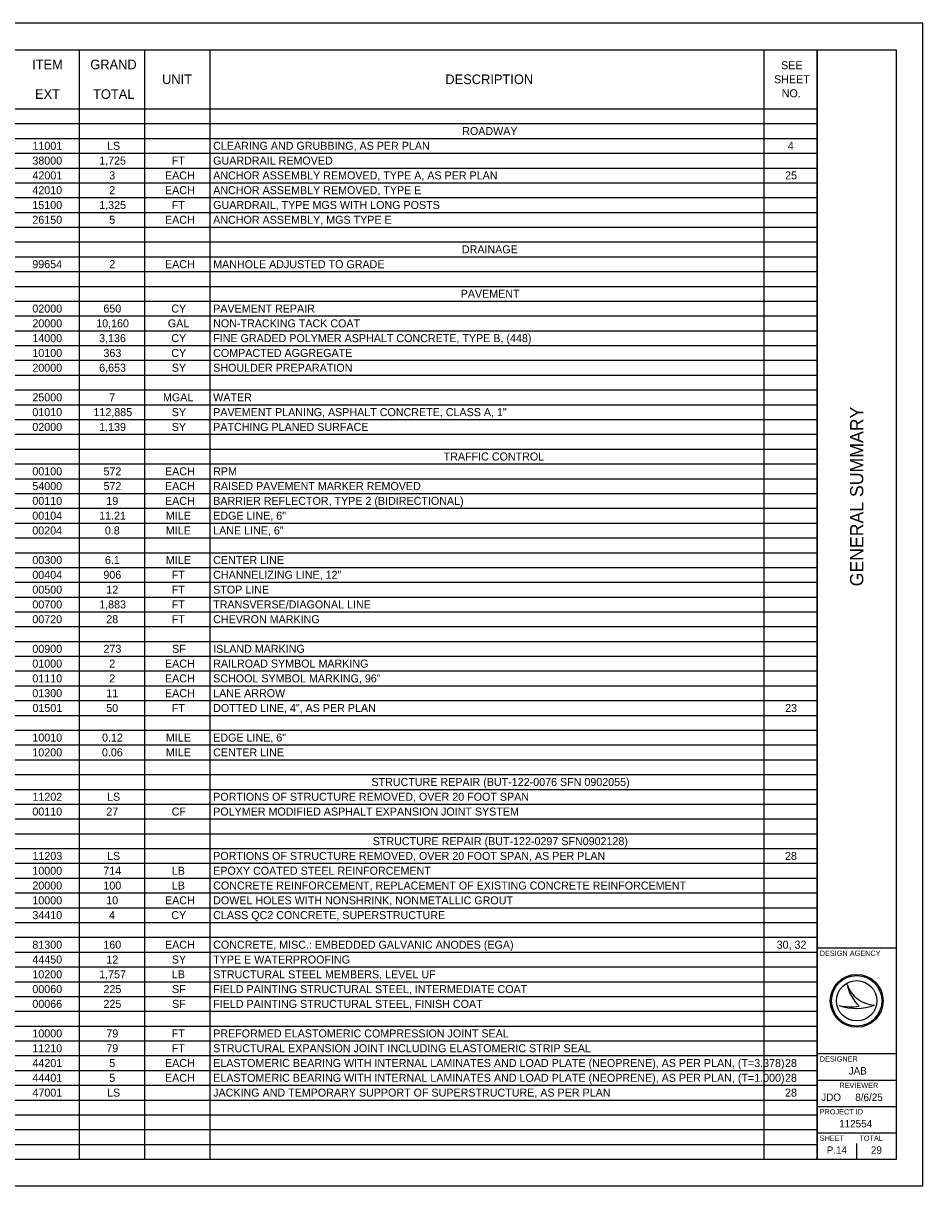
# Model space of a CAD drawing. Extents: x 45.7 to 120.9, y -0.1 to 21.9.
# Drawn here: x 62.68 to 79.7, y -0.09 to 21.91 of the extents above; entities that cross this region are included whole.
import ezdxf

# ---------------------------------------------------------------- set-up
doc = ezdxf.new("R2010")
doc.units = 0
for name, color, linetype in [('SH_Border', 7, 'Continuous'), ('SH_Cut_Line', 7, 'Continuous'), ('SH_Data', 7, 'Continuous'), ('SH_Text', 7, 'Continuous')]:
    doc.layers.add(name, color=color, linetype=linetype)

msp = doc.modelspace()

# ---------------------------------------------------------------- linework, layer by layer
at = {"layer": 'SH_Border'}
for p, q in [((77.703, 0.409), (77.703, 21.409)), ((77.703, 4.409), (79.203, 4.409)), ((77.703, 2.409), (79.203, 2.409)), ((77.703, 1.909), (79.203, 1.909)), ((77.703, 1.409), (79.203, 1.409)), ((77.703, 0.909), (79.203, 0.909))]:
    msp.add_line(p, q, dxfattribs=at)
msp.add_lwpolyline([(47.203, 21.409), (79.203, 21.409), (79.203, 0.409), (47.203, 0.409)], close=True, dxfattribs=at)
at = {"layer": 'SH_Cut_Line'}
msp.add_lwpolyline([(45.703, -0.091), (79.703, -0.091), (79.703, 21.909), (45.703, 21.909)], close=True, dxfattribs=at)
at = {"layer": 'SH_Data'}
for p, q in [((78.27, 3.719), (78.27, 3.719)), ((78.12, 3.319), (78.12, 3.319)), ((78.453, 3.409), (78.453, 3.409)), ((78.79, 3.328), (78.79, 3.328)), ((78.453, 0.409), (78.453, 0.709)), ((78.078, 0.584), (78.078, 0.584))]:
    msp.add_line(p, q, dxfattribs=at)
for radius in [0.5, 0.477, 0.477, 0.382]:
    msp.add_circle((78.453, 3.409), radius, dxfattribs=at)
for centre, radius, start, end in [((78.819, 3.907), 0.58, 198.9257, 198.9319), ((79.05, 3.879), 0.796, 191.6379, 191.6421), ((78.819, 3.907), 0.58, 198.9319, 267.1657), ((79.05, 3.879), 0.796, 191.6421, 226.0947), ((78.442, 4.279), 1.013, 251.4576, 290.0832), ((78.351, 4.563), 1.266, 259.4964, 259.4995), ((78.442, 4.279), 1.013, 251.4527, 251.4576), ((78.351, 4.563), 1.266, 259.4995, 276.6672)]:
    msp.add_arc(centre, radius, start, end, dxfattribs=at)
at = {"layer": 'SH_Text'}
for p, q in [((47.203, 21.409), (77.703, 21.409)), ((63.738, 21.409), (63.738, 0.412)), ((64.973, 21.409), (64.973, 0.412)), ((66.208, 21.409), (66.208, 0.412)), ((76.698, 21.409), (76.698, 0.412)), ((77.703, 21.409), (77.703, 0.412)), ((47.203, 20.289), (77.703, 20.289)), ((47.203, 20.009), (77.703, 20.009)), ((47.203, 19.729), (77.703, 19.729)), ((47.203, 19.449), (77.703, 19.449)), ((47.203, 19.169), (77.703, 19.169)), ((47.203, 18.889), (77.703, 18.889)), ((47.203, 18.609), (77.703, 18.609)), ((47.203, 18.33), (77.703, 18.33)), ((47.203, 18.05), (77.703, 18.05)), ((47.203, 17.77), (77.703, 17.77)), ((47.203, 17.49), (77.703, 17.49)), ((47.203, 17.21), (77.703, 17.21)), ((47.203, 16.93), (77.703, 16.93)), ((47.203, 16.65), (77.703, 16.65)), ((47.203, 16.37), (77.703, 16.37)), ((47.203, 16.09), (77.703, 16.09)), ((47.203, 15.81), (77.703, 15.81)), ((47.203, 15.53), (77.703, 15.53)), ((47.203, 15.25), (77.703, 15.25)), ((47.203, 14.97), (77.703, 14.97)), ((47.203, 14.69), (77.703, 14.69)), ((47.203, 14.41), (77.703, 14.41)), ((47.203, 14.13), (77.703, 14.13)), ((47.203, 13.85), (77.703, 13.85)), ((47.203, 13.57), (77.703, 13.57)), ((47.203, 13.29), (77.703, 13.29)), ((47.203, 13.01), (77.703, 13.01)), ((47.203, 12.73), (77.703, 12.73)), ((47.203, 12.45), (77.703, 12.45)), ((47.203, 12.17), (77.703, 12.17)), ((47.203, 11.89), (77.703, 11.89)), ((47.203, 11.61), (77.703, 11.61)), ((47.203, 11.33), (77.703, 11.33)), ((47.203, 11.05), (77.703, 11.05)), ((47.203, 10.77), (77.703, 10.77)), ((47.203, 10.49), (77.703, 10.49)), ((47.203, 10.21), (77.703, 10.21)), ((47.203, 9.93), (77.703, 9.93)), ((47.203, 9.651), (77.703, 9.651)), ((47.203, 9.371), (77.703, 9.371)), ((47.203, 9.091), (77.703, 9.091)), ((47.203, 8.811), (77.703, 8.811)), ((47.203, 8.531), (77.703, 8.531)), ((47.203, 8.251), (77.703, 8.251)), ((47.203, 7.971), (77.703, 7.971)), ((47.203, 7.691), (77.703, 7.691)), ((47.203, 7.411), (77.703, 7.411)), ((47.203, 7.131), (77.703, 7.131)), ((47.203, 6.851), (77.703, 6.851)), ((47.203, 6.571), (77.703, 6.571)), ((47.203, 6.291), (77.703, 6.291)), ((47.203, 6.011), (77.703, 6.011)), ((47.203, 5.731), (77.703, 5.731)), ((47.203, 5.451), (77.703, 5.451)), ((47.203, 5.171), (77.703, 5.171)), ((47.203, 4.891), (77.703, 4.891)), ((47.203, 4.611), (77.703, 4.611)), ((47.203, 4.331), (77.703, 4.331)), ((47.203, 4.051), (77.703, 4.051)), ((47.203, 3.771), (77.703, 3.771)), ((47.203, 3.491), (77.703, 3.491)), ((47.203, 3.211), (77.703, 3.211)), ((47.203, 2.931), (77.703, 2.931)), ((47.203, 2.651), (77.703, 2.651)), ((47.203, 2.371), (77.703, 2.371)), ((47.203, 2.091), (77.703, 2.091)), ((47.203, 1.811), (77.703, 1.811)), ((47.203, 1.531), (77.703, 1.531)), ((47.203, 1.251), (77.703, 1.251)), ((47.203, 0.972), (77.703, 0.972)), ((47.203, 0.692), (77.703, 0.692)), ((47.203, 0.412), (77.703, 0.412))]:
    msp.add_line(p, q, dxfattribs=at)

# ---------------------------------------------------------------- texts
at = {"layer": 'SH_Data'}
msp.add_text('GENERAL SUMMARY', height=0.25, rotation=90, dxfattribs=at).set_placement((78.578, 11.253))
for s, height, p in [('DESIGN AGENCY', 0.1, (77.753, 4.259)), ('DESIGNER', 0.1, (77.753, 2.259)), ('JAB', 0.14, (78.301, 2.014)), ('REVIEWER', 0.1, (78.125, 1.759)), ('JDO', 0.14, (77.782, 1.514)), ('8/6/25', 0.14, (78.426, 1.514)), ('PROJECT ID', 0.1, (77.753, 1.259)), ('112554', 0.14, (78.121, 1.014)), ('SHEET', 0.1, (77.753, 0.759)), ('TOTAL', 0.1, (78.503, 0.759)), ('P.14', 0.14, (77.885, 0.514)), ('29', 0.14, (78.722, 0.514))]:
    msp.add_text(s, height=height, dxfattribs=at).set_placement(p)
at = {"layer": 'SH_Text'}
for s, height, p in [('ITEM', 0.1818, (62.848, 21.038)), ('GRAND', 0.1818, (63.948, 21.038)), ('SEE ', 0.1515, (77.023, 21.039)), ('UNIT', 0.1818, (65.307, 20.758)), ('DESCRIPTION', 0.18181, (70.668, 20.758)), ('SHEET ', 0.1515, (76.89, 20.773)), ('EXT', 0.1818, (62.902, 20.478)), ('TOTAL', 0.1818, (64, 20.478)), ('NO.', 0.1515, (77.034, 20.508)), ('ROADWAY', 0.1515, (70.987, 19.794)), ('11001', 0.1515, (62.854, 19.514)), ('LS', 0.1515, (64.265, 19.514)), ('CLEARING AND GRUBBING, AS PER PLAN', 0.15151, (66.274, 19.514)), ('4', 0.152, (77.149, 19.514)), ('38000', 0.1515, (62.852, 19.234)), ('1,725', 0.1515, (64.117, 19.234)), ('FT', 0.1515, (65.489, 19.234)), ('GUARDRAIL REMOVED', 0.15151, (66.274, 19.234)), ('42001', 0.1515, (62.854, 18.954)), ('3', 0.152, (64.307, 18.954)), ('EACH', 0.1515, (65.362, 18.954)), ('ANCHOR ASSEMBLY REMOVED, TYPE A, AS PER PLAN', 0.15151, (66.274, 18.954)), ('25', 0.1515, (77.098, 18.954)), ('42010', 0.1515, (62.852, 18.674)), ('2', 0.152, (64.307, 18.674)), ('EACH', 0.1515, (65.362, 18.674)), ('ANCHOR ASSEMBLY REMOVED, TYPE E', 0.15151, (66.274, 18.674)), ('15100', 0.1515, (62.852, 18.394)), ('1,325', 0.1515, (64.117, 18.394)), ('FT', 0.1515, (65.489, 18.394)), ('GUARDRAIL, TYPE MGS WITH LONG POSTS', 0.15151, (66.274, 18.394)), ('26150', 0.1515, (62.852, 18.114)), ('5', 0.152, (64.307, 18.114)), ('EACH', 0.1515, (65.362, 18.114)), ('ANCHOR ASSEMBLY, MGS TYPE E', 0.15151, (66.274, 18.114)), ('DRAINAGE', 0.1515, (70.981, 17.554)), ('99654', 0.1515, (62.851, 17.274)), ('2', 0.152, (64.307, 17.274)), ('EACH', 0.1515, (65.362, 17.274)), ('MANHOLE ADJUSTED TO GRADE', 0.15151, (66.274, 17.274)), ('PAVEMENT', 0.1515, (70.958, 16.714)), ('02000', 0.1515, (62.852, 16.434)), ('650', 0.1515, (64.196, 16.434)), ('CY', 0.1515, (65.482, 16.434)), ('PAVEMENT REPAIR', 0.15151, (66.274, 16.434)), ('20000', 0.1515, (62.852, 16.154)), ('10,160', 0.1515, (64.06, 16.154)), ('GAL', 0.1515, (65.416, 16.154)), ('NON-TRACKING TACK COAT', 0.15151, (66.274, 16.154)), ('14000', 0.1515, (62.852, 15.874)), ('3,136', 0.1515, (64.115, 15.874)), ('CY', 0.1515, (65.482, 15.874)), ('FINE GRADED POLYMER ASPHALT CONCRETE, TYPE B, (448)', 0.15151, (66.274, 15.874)), ('10100', 0.1515, (62.852, 15.594)), ('363', 0.1515, (64.198, 15.594)), ('CY', 0.1515, (65.482, 15.594)), ('COMPACTED AGGREGATE', 0.15151, (66.274, 15.594)), ('20000', 0.1515, (62.852, 15.314)), ('6,653', 0.1515, (64.117, 15.314)), ('SY', 0.1515, (65.491, 15.314)), ('SHOULDER PREPARATION', 0.15151, (66.274, 15.314)), ('25000', 0.1515, (62.852, 14.754)), ('7', 0.152, (64.306, 14.754)), ('MGAL', 0.1515, (65.324, 14.754)), ('WATER', 0.1515, (66.274, 14.754)), ('01010', 0.1515, (62.852, 14.474)), ('112,885', 0.1515, (64.008, 14.474)), ('SY', 0.1515, (65.491, 14.474)), ('PAVEMENT PLANING, ASPHALT CONCRETE, CLASS A, 1"', 0.15151, (66.274, 14.474)), ('02000', 0.1515, (62.852, 14.194)), ('1,139', 0.1515, (64.116, 14.194)), ('SY', 0.1515, (65.491, 14.194)), ('PATCHING PLANED SURFACE', 0.15151, (66.274, 14.194)), ('TRAFFIC CONTROL', 0.15151, (70.636, 13.634)), ('00100', 0.1515, (62.852, 13.354)), ('572', 0.1515, (64.198, 13.354)), ('EACH', 0.1515, (65.362, 13.354)), ('RPM', 0.1515, (66.274, 13.354)), ('54000', 0.1515, (62.852, 13.074)), ('572', 0.1515, (64.198, 13.074)), ('EACH', 0.1515, (65.362, 13.074)), ('RAISED PAVEMENT MARKER REMOVED', 0.15151, (66.274, 13.074)), ('00110', 0.1515, (62.852, 12.794)), ('19', 0.1515, (64.252, 12.794)), ('EACH', 0.1515, (65.362, 12.794)), ('BARRIER REFLECTOR, TYPE 2 (BIDIRECTIONAL)', 0.15151, (66.274, 12.794)), ('00104', 0.1515, (62.851, 12.514)), ('11.21', 0.1515, (64.116, 12.514)), ('MILE', 0.1515, (65.379, 12.514)), ('EDGE LINE, 6"', 0.15151, (66.274, 12.514)), ('00204', 0.1515, (62.851, 12.234)), ('0.8', 0.1515, (64.224, 12.234)), ('MILE', 0.1515, (65.379, 12.234)), ('LANE LINE, 6"', 0.15151, (66.274, 12.234)), ('00300', 0.1515, (62.852, 11.675)), ('6.1', 0.1515, (64.225, 11.675)), ('MILE', 0.1515, (65.379, 11.675)), ('CENTER LINE', 0.15151, (66.274, 11.675)), ('00404', 0.1515, (62.851, 11.395)), ('906', 0.1515, (64.196, 11.395)), ('FT', 0.1515, (65.489, 11.395)), ('CHANNELIZING LINE, 12"', 0.15151, (66.274, 11.395)), ('00500', 0.1515, (62.852, 11.115)), ('12', 0.1515, (64.252, 11.115)), ('FT', 0.1515, (65.489, 11.115)), ('STOP LINE', 0.1515, (66.274, 11.115)), ('00700', 0.1515, (62.852, 10.835)), ('1,883', 0.1515, (64.117, 10.835)), ('FT', 0.1515, (65.489, 10.835)), ('TRANSVERSE/DIAGONAL LINE', 0.15151, (66.274, 10.835)), ('00720', 0.1515, (62.852, 10.555)), ('28', 0.1515, (64.251, 10.555)), ('FT', 0.1515, (65.489, 10.555)), ('CHEVRON MARKING', 0.15151, (66.274, 10.555)), ('00900', 0.1515, (62.852, 9.995)), ('273', 0.1515, (64.198, 9.995)), ('SF', 0.1515, (65.496, 9.995)), ('ISLAND MARKING', 0.15151, (66.274, 9.995)), ('01000', 0.1515, (62.852, 9.715)), ('2', 0.152, (64.307, 9.715)), ('EACH', 0.1515, (65.362, 9.715)), ('RAILROAD SYMBOL MARKING', 0.15151, (66.274, 9.715)), ('01110', 0.1515, (62.852, 9.435)), ('2', 0.152, (64.307, 9.435)), ('EACH', 0.1515, (65.362, 9.435)), ('SCHOOL SYMBOL MARKING, 96"', 0.15151, (66.274, 9.435)), ('01300', 0.1515, (62.852, 9.155)), ('11', 0.1515, (64.252, 9.155)), ('EACH', 0.1515, (65.362, 9.155)), ('LANE ARROW', 0.1515, (66.274, 9.155)), ('01501', 0.1515, (62.854, 8.875)), ('50', 0.1515, (64.25, 8.875)), ('FT', 0.1515, (65.489, 8.875)), ('DOTTED LINE, 4", AS PER PLAN', 0.15151, (66.274, 8.875)), ('23', 0.1515, (77.098, 8.875)), ('10010', 0.1515, (62.852, 8.315)), ('0.12', 0.1515, (64.171, 8.315)), ('MILE', 0.1515, (65.379, 8.315)), ('EDGE LINE, 6"', 0.15151, (66.274, 8.315)), ('10200', 0.1515, (62.852, 8.035)), ('0.06', 0.1515, (64.169, 8.035)), ('MILE', 0.1515, (65.379, 8.035)), ('CENTER LINE', 0.15151, (66.274, 8.035)), ('STRUCTURE REPAIR (BUT-122-0076 SFN 0902055)', 0.15151, (69.269, 7.475)), ('11202', 0.1515, (62.854, 7.195)), ('LS', 0.1515, (64.265, 7.195)), ('PORTIONS OF STRUCTURE REMOVED, OVER 20 FOOT SPAN', 0.15151, (66.274, 7.195)), ('00110', 0.1515, (62.852, 6.915)), ('27', 0.1515, (64.251, 6.915)), ('CF', 0.1515, (65.488, 6.915)), ('POLYMER MODIFIED ASPHALT EXPANSION JOINT SYSTEM', 0.15151, (66.274, 6.915)), ('STRUCTURE REPAIR (BUT-122-0297 SFN0902128)', 0.15151, (69.293, 6.355)), ('11203', 0.1515, (62.854, 6.075)), ('LS', 0.1515, (64.265, 6.075)), ('PORTIONS OF STRUCTURE REMOVED, OVER 20 FOOT SPAN, AS PER PLAN', 0.15151, (66.274, 6.075)), ('28', 0.1515, (77.096, 6.075)), ('10000', 0.1515, (62.852, 5.795)), ('714', 0.1515, (64.195, 5.795)), ('LB', 0.1515, (65.491, 5.795)), ('EPOXY COATED STEEL REINFORCEMENT', 0.15151, (66.274, 5.795)), ('20000', 0.1515, (62.852, 5.515)), ('100', 0.1515, (64.196, 5.515)), ('LB', 0.1515, (65.491, 5.515)), ('CONCRETE REINFORCEMENT, REPLACEMENT OF EXISTING CONCRETE REINFORCEMENT', 0.15151, (66.274, 5.515)), ('10000', 0.1515, (62.852, 5.235)), ('10', 0.1515, (64.25, 5.235)), ('EACH', 0.1515, (65.362, 5.235)), ('DOWEL HOLES WITH NONSHRINK, NONMETALLIC GROUT', 0.15151, (66.274, 5.235)), ('34410', 0.1515, (62.852, 4.955)), ('4', 0.152, (64.304, 4.955)), ('CY', 0.1515, (65.482, 4.955)), ('CLASS QC2 CONCRETE, SUPERSTRUCTURE', 0.15151, (66.274, 4.955)), ('81300', 0.1515, (62.852, 4.395)), ('160', 0.1515, (64.196, 4.395)), ('EACH', 0.1515, (65.362, 4.395)), ('CONCRETE, MISC.: EMBEDDED GALVANIC ANODES (EGA)', 0.15151, (66.274, 4.395)), ('30, 32', 0.1515, (76.938, 4.395)), ('44450', 0.1515, (62.852, 4.115)), ('12', 0.1515, (64.252, 4.115)), ('SY', 0.1515, (65.491, 4.115)), ('TYPE E WATERPROOFING', 0.15151, (66.274, 4.115)), ('10200', 0.1515, (62.852, 3.835)), ('1,757', 0.1515, (64.116, 3.835)), ('LB', 0.1515, (65.491, 3.835)), ('STRUCTURAL STEEL MEMBERS, LEVEL UF', 0.15151, (66.274, 3.835)), ('00060', 0.1515, (62.852, 3.555)), ('225', 0.1515, (64.198, 3.555)), ('SF', 0.1515, (65.496, 3.555)), ('FIELD PAINTING STRUCTURAL STEEL, INTERMEDIATE COAT', 0.15151, (66.274, 3.555)), ('00066', 0.1515, (62.852, 3.275)), ('225', 0.1515, (64.198, 3.275)), ('SF', 0.1515, (65.496, 3.275)), ('FIELD PAINTING STRUCTURAL STEEL, FINISH COAT', 0.15151, (66.274, 3.275)), ('10000', 0.1515, (62.852, 2.716)), ('79', 0.1515, (64.252, 2.716)), ('FT', 0.1515, (65.489, 2.716)), ('PREFORMED ELASTOMERIC COMPRESSION JOINT SEAL', 0.15151, (66.274, 2.716)), ('11210', 0.1515, (62.852, 2.436)), ('79', 0.1515, (64.252, 2.436)), ('FT', 0.1515, (65.489, 2.436)), ('STRUCTURAL EXPANSION JOINT INCLUDING ELASTOMERIC STRIP SEAL', 0.15151, (66.274, 2.436)), ('44201', 0.1515, (62.854, 2.156)), ('5', 0.152, (64.307, 2.156)), ('EACH', 0.1515, (65.362, 2.156)), ('ELASTOMERIC BEARING WITH INTERNAL LAMINATES AND LOAD PLATE (NEOPRENE), AS PER PLAN, (T=3.378)', 0.15151, (66.274, 2.156)), ('28', 0.1515, (77.096, 2.156)), ('44401', 0.1515, (62.854, 1.876)), ('5', 0.152, (64.307, 1.876)), ('EACH', 0.1515, (65.362, 1.876)), ('ELASTOMERIC BEARING WITH INTERNAL LAMINATES AND LOAD PLATE (NEOPRENE), AS PER PLAN, (T=1.000)', 0.15151, (66.274, 1.876)), ('28', 0.1515, (77.096, 1.876)), ('47001', 0.1515, (62.854, 1.596)), ('LS', 0.1515, (64.265, 1.596)), ('JACKING AND TEMPORARY SUPPORT OF SUPERSTRUCTURE, AS PER PLAN', 0.15151, (66.274, 1.596)), ('28', 0.1515, (77.096, 1.596))]:
    msp.add_text(s, height=height, dxfattribs=at).set_placement(p)

doc.saveas('drawing.dxf')
